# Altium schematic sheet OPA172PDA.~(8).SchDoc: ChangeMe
size 431 x 279 mm; Date: Not shown in title block; ApprovedBy: Not shown in title block; CheckedBy: Not shown in title block; Author: Not shown in title block; CompanyName: Not shown in title block; DrawnBy: Enter Full Name; Engineer: Not shown in title block; Organization: Not shown in title block; Address1: Not shown in title block; Address2: Not shown in title block; Address3: Not shown in title block; Address4: Not shown in title block; DocumentNumber: 2; Revision: Use project parameter SCH_Rev; SheetNumber: 2; SheetTotal: 3; PageSetup: Record=PageOptions|CenterHorizontal=True|CenterVertical=True|PrintScale=1.00|XCorrection=1.00|YCorrection=1.00|PrintKind=0|BorderSize=5000000|LeftOffset=0|BottomOffset=0|Orientation=2|PaperLength=1000|PaperWidth=1000|Scale=100|PaperSource=15|PrintQuality=600|MediaType=1|DitherType=10|PaperKind=Letter|PrintScaleMode=1
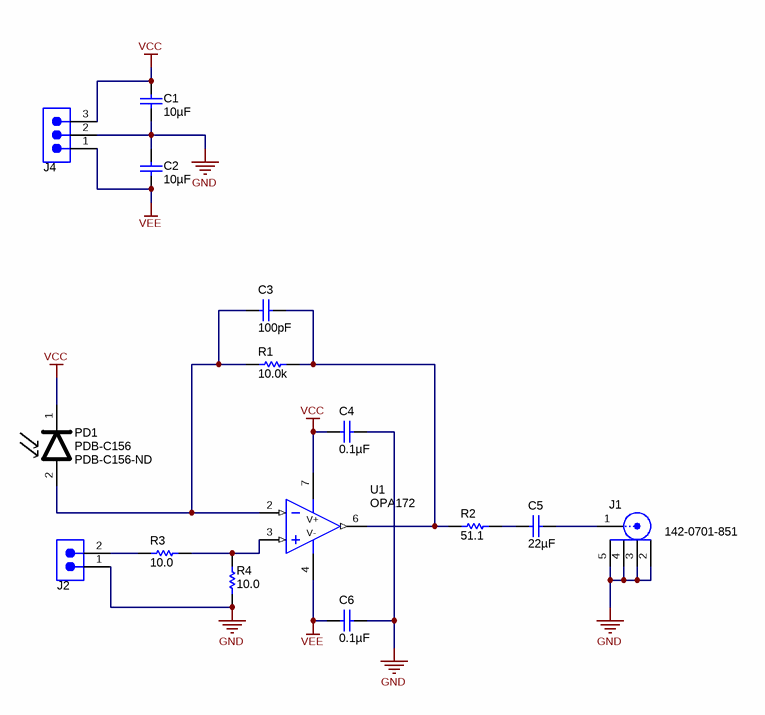
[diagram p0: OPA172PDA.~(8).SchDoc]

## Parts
C1  ValueDisplayed: 10µF  [1210]  (hidden comment: C1210C106K8PACTU)
C2  ValueDisplayed: 10µF  [1210]  (hidden comment: C1210C106K8PACTU)
C3  ValueDisplayed: 100pF  [0603]  (hidden comment: 06033C101KAT2A)
C4  ValueDisplayed: 0.1µF  [0603]  (hidden comment: 0603YC104JAT2A)
C5  ValueDisplayed: 22µF  [1210]  (hidden comment: 12103D226MAT2A)
C6  ValueDisplayed: 0.1µF  [0603]  (hidden comment: 0603YC104JAT2A)
J1  142-0701-851  [Emerson_142-0701-851]
J2  TSW-102-07-G-S  [TSW-102-07-G-S]  (value not drawn)
J4  TSW-103-07-G-S  [TSW-103-07-G-S]  (value not drawn)
PD1  PDB-C156  Supplier Part Number 1: PDB-C156-ND  [PDB-C156]
R1  value 10.0k  [0603]  (hidden comment: CRCW060310K0FKEA)
R2  value 51.1  [0603]  (hidden comment: CRCW060351R1FKEA)
R3  value 10.0  [0603]  (hidden comment: CRCW060310R0FKEA)
R4  value 10.0  [0603]  (hidden comment: CRCW060310R0FKEA)
U1  OPA172  [M08A_M]

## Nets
GND: C1.2 C2.1 C4.1 C6.1 J1.2 J1.3 J1.4 J1.5 J2.1 J4.2 R4.1
VCC: C1.1 C4.2 J4.3 PD1.1(C) U1.7(V+)
VEE: C2.2 C6.2 J4.1 U1.4(V-)
NetC3_1: C3.1 R1.2 R2.1 U1.6(OUT)
NetC3_2: C3.2 PD1.2(A) R1.1 U1.2(IN-)
NetC5_1: C5.1 J1.1
NetC5_2: C5.2 R2.2
NetJ2_2: J2.2 R3.1
NetR3_2: R3.2 R4.2 U1.3(IN+)

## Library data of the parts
C1 C2 = C1210C106K8PACTU: CAP, CERM, 10uF, 10V, +/-10%, X5R, 1210; Manufacturer: Kemet; Polarized: N; CompType: Capacitor; U/M: EA; Cap_F: 0.00001; Tolerance_%: 10; ESR_Ohm: 0.008; Value1: 0.008 ohm; IRMS_A: 6.9; TaMin_C: -55; TaMax_C: 85
C3 = 06033C101KAT2A: CAP, CERM, 100pF, 25V, +/-10%, X7R, 0603; Manufacturer: AVX; Polarized: N; CompType: Capacitor; U/M: EA; Cap_F: 0.0000000001; Tolerance_%: 10; VDC_V: 25; TaMin_C: -55; TaMax_C: 125
C4 C6 = 0603YC104JAT2A: CAP, CERM, 0.1uF, 16V, +/-5%, X7R, 0603; Manufacturer: AVX; Polarized: N; CompType: Capacitor; U/M: EA; Cap_F: 0.0000001; Tolerance_%: 5; ESR_Ohm: 0.039; Value1: 0.039 ohm; VDC_V: 16; TaMin_C: -55; TaMax_C: 125
C5 = 12103D226MAT2A: CAP, CERM, 22uF, 25V, +/-20%, X5R, 1210; Manufacturer: AVX; Polarized: N; CompType: Capacitor; U/M: EA; Cap_F: 0.000022; Tolerance_%: 20; VDC_V: 25; TaMin_C: -55; TaMax_C: 85
J1 = 142-0701-851: Connector, SMT, End launch SMA 50 ohm; Manufacturer: Emerson Network Power; Alternate Manufacturer: Any; Alternate PartNumber: Equivalent; U/M: EA
J2 = TSW-102-07-G-S: Header, TH, 100mil, 2x1, Gold plated, 230 mil above insulator; Manufacturer: Samtec, Inc.; Alternate Manufacturer: Any; Alternate PartNumber: Equivalent; U/M: EA
J4 = TSW-103-07-G-S: Header, TH, 100mil, 3x1, Gold plated, 230 mil above insulator; Manufacturer: Samtec, Inc.; Alternate Manufacturer: Any; Alternate PartNumber: Equivalent; U/M: EA
PD1 = PDB-C156: Photodiode; Manufacturer: Used in BOM report; SymbolVersion: use current date i.e. 2008-05-20; SymbolCreator: Use LDAP id; CompType: Used in some BOM reports.  Useful for finding later.; U/M: EA, IN, or GM
R1 = CRCW060310K0FKEA: RES, 10.0k ohm, 1%, 0.1W, 0603; Manufacturer: Vishay-Dale; Alternate Manufacturer: Any; Alternate PartNumber: Equivalent; CompType: Resistor; Res_ohm: 10000; Value_Code: 10k0; Tolerance_%: 1; Power_W: 0.1; VDC_V: 75; TempCo: 100 ppm/C; EIA_Code: E96; U/M: EA
R2 = CRCW060351R1FKEA: RES, 51.1 ohm, 1%, 0.1W, 0603; Manufacturer: Vishay-Dale; Alternate Manufacturer: Any; Alternate PartNumber: Equivalent; CompType: Resistor; Value_Code: 51R1; Tolerance_%: 1; Power_W: 0.1; VDC_V: 75; TempCo: 100 ppm/C; EIA_Code: E96; U/M: EA
R3 R4 = CRCW060310R0FKEA: RES, 10.0 ohm, 1%, 0.1W, 0603; Manufacturer: Vishay-Dale; Alternate Manufacturer: Any; Alternate PartNumber: Equivalent; CompType: Resistor; Res_ohm: 10; Value_Code: 10R0; Tolerance_%: 1; Power_W: 0.1; VDC_V: 75; TempCo: 100 ppm/C; EIA_Code: E96; U/M: EA
U1 = OPA172: Manufacturer: Used in BOM report; SymbolVersion: use current date i.e. 2008-05-20; SymbolCreator: Use LDAP id; CompType: Used in some BOM reports.  Useful for finding later.; U/M: EA, IN, or GM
